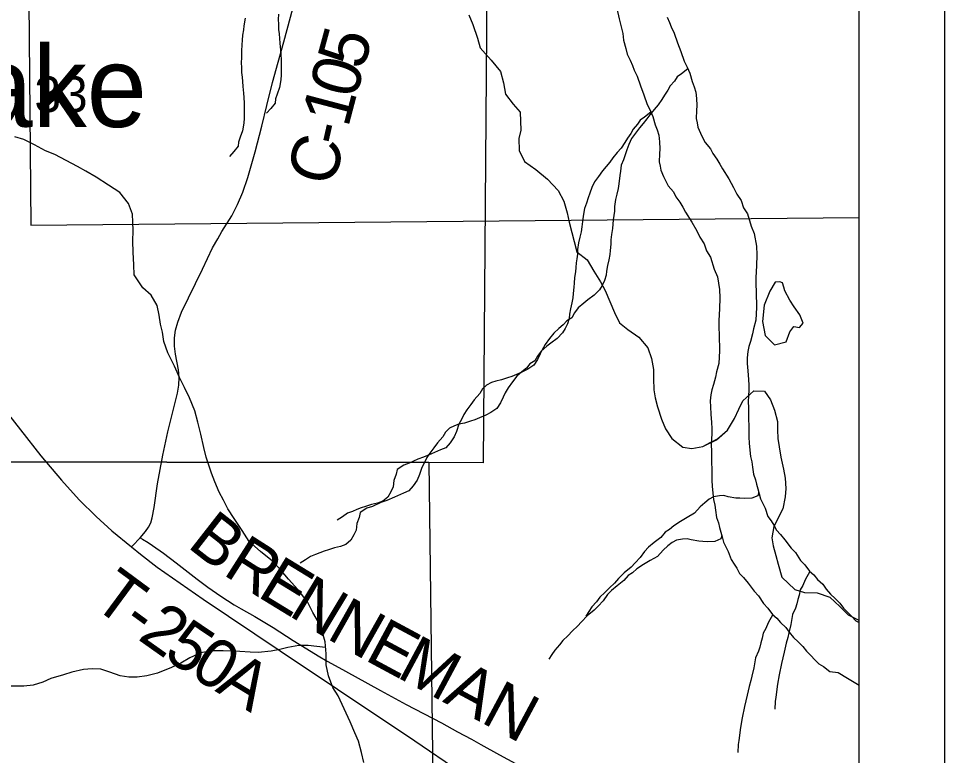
# Model space of a CAD drawing. Extents: x -21.1 to 50.3, y -4.9 to 22.1.
# Drawn here: x 7.916 to 9, y 16.789 to 17.651 of the extents above; entities that cross this region are included whole.
import ezdxf

# ---------------------------------------------------------------- set-up
doc = ezdxf.new("R2010")
doc.units = 0
for name, color, linetype in [('GM_X_Corporation', 7, 'Continuous'), ('GM_X_County', 7, 'Continuous'), ('GM_X_County_Road', 7, 'Continuous'), ('GM_X_County_Road_Text', 7, 'Continuous'), ('GM_X_Major_Lake', 7, 'Continuous'), ('GM_X_Major_Lake_Text', 7, 'Continuous'), ('GM_X_Minor_River', 7, 'Continuous'), ('GM_X_Rail_Line_Text', 7, 'Continuous'), ('GM_X_Section', 7, 'Continuous'), ('GM_X_Section_Text', 7, 'Continuous'), ('GM_X_Township_Road', 7, 'Continuous'), ('GM_X_Township_Road_Text', 7, 'Continuous'), ('GM_X_US_Route', 7, 'Continuous'), ('SH_Cut_Line', 7, 'Continuous'), ('SH_Data', 7, 'Continuous')]:
    doc.layers.add(name, color=color, linetype=linetype)

msp = doc.modelspace()

# ---------------------------------------------------------------- linework, layer by layer
at = {"layer": 'GM_X_Corporation'}
msp.add_lwpolyline([(8.9, 17.418), (8.9, 18.4235), (7.9213, 18.4125), (7.9303, 17.4089)], close=True, dxfattribs=at)
at = {"layer": 'GM_X_County'}
msp.add_lwpolyline([(8.9, 14.7464), (8.9, 20.9), (2.1, 20.9), (2.1, 14.1), (8.8932, 14.1)], dxfattribs=at)
at = {"layer": 'GM_X_County_Road'}
for points in [[(8.0586, 17.0433), (8.0647, 17.0505), (8.0681, 17.0555), (8.0708, 17.0609), (8.0726, 17.0667), (8.0748, 17.0788), (8.0788, 17.1064), (8.0851, 17.14), (8.0908, 17.1673), (8.102, 17.2126), (8.1036, 17.2217), (8.1041, 17.2308), (8.1032, 17.2399), (8.0997, 17.2582), (8.0986, 17.2676), (8.0986, 17.277), (8.0998, 17.2863), (8.1024, 17.2954), (8.107, 17.307), (8.1313, 17.3573), (8.1432, 17.3824), (8.1492, 17.3931), (8.1542, 17.4014), (8.1656, 17.4197), (8.1725, 17.4333), (8.1785, 17.4474), (8.1846, 17.4649), (8.1932, 17.4946), (8.201, 17.5247), (8.2067, 17.5488), (8.2134, 17.5758), (8.2266, 17.6235), (8.2411, 17.6773)], [(8.0482, 17.0326), (8.0493, 17.0337), (8.0586, 17.0433)]]:
    msp.add_lwpolyline(points, dxfattribs=at)
at = {"layer": 'GM_X_Major_Lake'}
for points in [[(8.4431, 17.6549), (8.4477, 17.6439), (8.4534, 17.6279), (8.4564, 17.6166), (8.4693, 17.6018), (8.4802, 17.5889), (8.4836, 17.5756), (8.4863, 17.5623), (8.495, 17.5506), (8.5033, 17.5411), (8.5039, 17.5201)], [(8.5039, 17.5201), (8.5016, 17.5103), (8.5023, 17.4962), (8.5082, 17.4833), (8.5215, 17.4741), (8.5354, 17.4626), (8.5479, 17.4496), (8.5542, 17.4371), (8.5583, 17.4234), (8.5605, 17.4124), (8.5698, 17.3776)], [(8.5698, 17.3776), (8.5819, 17.3683), (8.5894, 17.3553), (8.5973, 17.3427), (8.6029, 17.3325), (8.6081, 17.3195), (8.6137, 17.3066), (8.6197, 17.2948), (8.6295, 17.2868), (8.642, 17.278), (8.6529, 17.2654), (8.657, 17.2529), (8.6592, 17.24), (8.6595, 17.2297), (8.6598, 17.2164), (8.6613, 17.2069), (8.6639, 17.1963), (8.6687, 17.1819), (8.6736, 17.1708), (8.6807, 17.1594), (8.6936, 17.1491), (8.7042, 17.1475), (8.7171, 17.1501), (8.7332, 17.1579)], [(8.5698, 17.3776), (8.5819, 17.3683), (8.5894, 17.3553), (8.5973, 17.3427), (8.6029, 17.3325), (8.6081, 17.3195), (8.6137, 17.3066), (8.6197, 17.2948), (8.6295, 17.2868), (8.642, 17.278), (8.6529, 17.2654), (8.657, 17.2529), (8.6592, 17.24), (8.6595, 17.2297), (8.6598, 17.2164), (8.6613, 17.2069), (8.6639, 17.1963), (8.6687, 17.1819), (8.6736, 17.1708), (8.6807, 17.1594), (8.6936, 17.1491), (8.7042, 17.1475), (8.7171, 17.1501), (8.7266, 17.155)], [(8.5698, 17.3776), (8.5819, 17.3683), (8.5894, 17.3553), (8.5973, 17.3427), (8.6029, 17.3325), (8.6081, 17.3195), (8.6137, 17.3066), (8.6197, 17.2948), (8.6295, 17.2868), (8.642, 17.278), (8.6529, 17.2654), (8.657, 17.2529), (8.6592, 17.24), (8.6595, 17.2297), (8.6598, 17.2164), (8.6613, 17.2069), (8.6639, 17.1963), (8.6687, 17.1819), (8.6736, 17.1708), (8.6807, 17.1594), (8.6936, 17.1491), (8.7042, 17.1475), (8.7171, 17.1501), (8.7343, 17.1589)], [(8.8018, 17.3421), (8.7957, 17.3318), (8.7888, 17.3155), (8.7869, 17.2961), (8.7899, 17.2798), (8.8009, 17.2688), (8.8146, 17.2726), (8.8188, 17.2843), (8.8237, 17.2904), (8.8302, 17.2893), (8.8347, 17.2942), (8.8306, 17.3041), (8.8241, 17.3136), (8.8188, 17.3212)], [(8.8188, 17.3212), (8.8132, 17.3322), (8.8121, 17.3366), (8.8102, 17.3414), (8.8073, 17.3428), (8.8018, 17.3421)], [(8.7332, 17.1579), (8.7458, 17.1693), (8.7541, 17.1826), (8.7591, 17.1936), (8.764, 17.2035), (8.7769, 17.2152), (8.7895, 17.2148), (8.7963, 17.2046), (8.8012, 17.1924), (8.8046, 17.1791), (8.8046, 17.1696), (8.805, 17.1594), (8.8065, 17.1495), (8.8084, 17.1377), (8.8114, 17.1237), (8.8136, 17.1131), (8.8144, 17.1009), (8.8136, 17.091), (8.8106, 17.077), (8.8003, 17.0565), (8.798, 17.0432), (8.7995, 17.0337), (8.8025, 17.0227), (8.8052, 17.0124), (8.8097, 16.9972), (8.8249, 16.9828), (8.8363, 16.9794), (8.8511, 16.979), (8.8659, 16.9737), (8.8776, 16.963), (8.8871, 16.9531), (8.8974, 16.9482), (8.9, 16.9464)], [(8.7343, 17.1589), (8.7458, 17.1693), (8.7541, 17.1826), (8.7591, 17.1936), (8.764, 17.2035), (8.7769, 17.2152), (8.7895, 17.2148), (8.7963, 17.2046), (8.8012, 17.1924), (8.8046, 17.1791), (8.8046, 17.1696), (8.805, 17.1594), (8.8065, 17.1495), (8.8084, 17.1377), (8.8114, 17.1237), (8.8136, 17.1131), (8.8144, 17.1009), (8.8136, 17.091), (8.8106, 17.077), (8.8003, 17.0565), (8.798, 17.0432), (8.7995, 17.0337), (8.8025, 17.0227), (8.8052, 17.0124), (8.8097, 16.9972), (8.8249, 16.9828), (8.8363, 16.9794), (8.8511, 16.979), (8.8659, 16.9737), (8.8776, 16.963), (8.8871, 16.9531), (8.8974, 16.9482), (8.9, 16.9464)]]:
    msp.add_lwpolyline(points, dxfattribs=at)
at = {"layer": 'GM_X_Minor_River'}
for points in [[(8.6163, 17.6625), (8.619, 17.6503), (8.6218, 17.6393), (8.6233, 17.6333), (8.6241, 17.6253), (8.6268, 17.6158), (8.6284, 17.609), (8.6319, 17.6018), (8.6346, 17.5957), (8.6369, 17.5904), (8.6403, 17.5832), (8.6442, 17.5718), (8.6481, 17.5616), (8.6519, 17.5502), (8.6554, 17.5434), (8.6585, 17.5362), (8.6612, 17.5263), (8.6635, 17.5203), (8.6655, 17.5142), (8.6663, 17.5066), (8.6667, 17.4983), (8.6664, 17.4926), (8.666, 17.4831), (8.6672, 17.4781), (8.668, 17.4732), (8.6711, 17.466), (8.6738, 17.4603), (8.6765, 17.455), (8.6826, 17.4478), (8.6857, 17.4421), (8.6903, 17.4357), (8.6937, 17.43), (8.6968, 17.4243), (8.7041, 17.4126), (8.7099, 17.4024), (8.7137, 17.3948), (8.7187, 17.3872), (8.7214, 17.3789), (8.726, 17.3717), (8.7303, 17.3573), (8.7341, 17.3486), (8.7365, 17.3338), (8.7369, 17.3239), (8.7366, 17.311), (8.736, 17.2973), (8.736, 17.2893), (8.7364, 17.2806), (8.7365, 17.262), (8.7359, 17.2472), (8.7332, 17.2373), (8.7321, 17.2312), (8.7295, 17.2224), (8.7276, 17.2163), (8.7265, 17.2106), (8.7258, 17.2034), (8.7259, 17.1966), (8.7263, 17.1878), (8.7271, 17.178), (8.7275, 17.1711), (8.7276, 17.1662), (8.7272, 17.1578), (8.7269, 17.1525), (8.7273, 17.1442), (8.7275, 17.1107), (8.7279, 17.1031), (8.7295, 17.0879), (8.7311, 17.0815), (8.7319, 17.0754), (8.7331, 17.0671), (8.7354, 17.0606), (8.7365, 17.0553), (8.7381, 17.05), (8.7396, 17.0443), (8.7412, 17.0382), (8.7466, 17.0273), (8.7501, 17.0178), (8.7539, 17.0125), (8.757, 17.0076), (8.7601, 17.0015), (8.7647, 16.9966), (8.77, 16.9902), (8.7773, 16.9807), (8.7823, 16.9754), (8.788, 16.9663), (8.7934, 16.961), (8.7988, 16.9535), (8.8037, 16.9493), (8.808, 16.944), (8.8141, 16.9384), (8.8183, 16.9327), (8.8233, 16.9266), (8.8286, 16.9217), (8.834, 16.9161), (8.8386, 16.9104), (8.8436, 16.9055)], [(8.1813, 17.6513), (8.1798, 17.6422), (8.1795, 17.6373), (8.1784, 17.6312), (8.178, 17.6255), (8.1773, 17.6198), (8.1769, 17.6129), (8.177, 17.6053), (8.1766, 17.5989), (8.177, 17.5936), (8.1771, 17.5875), (8.1779, 17.5822), (8.1783, 17.5769), (8.1787, 17.5712), (8.1795, 17.5632), (8.1799, 17.5583), (8.1803, 17.5518), (8.18, 17.5457), (8.18, 17.5343), (8.1797, 17.5282), (8.1782, 17.5195), (8.1756, 17.5119), (8.1737, 17.5062), (8.173, 17.5012), (8.1681, 17.4951), (8.1632, 17.4894)], [(8.2203, 17.6559), (8.2199, 17.6494), (8.2203, 17.6441), (8.2204, 17.638), (8.2212, 17.6327), (8.2216, 17.6274), (8.222, 17.6217), (8.2228, 17.6137), (8.2232, 17.6088), (8.2236, 17.6023), (8.2233, 17.5962), (8.2233, 17.5848), (8.223, 17.5788), (8.2215, 17.57), (8.2189, 17.5624), (8.217, 17.5567), (8.2163, 17.5518), (8.2114, 17.5456), (8.2064, 17.5399)], [(8.6752, 17.6523), (8.6779, 17.6462), (8.6802, 17.6409), (8.6836, 17.6337), (8.6875, 17.6224), (8.6914, 17.6121), (8.6952, 17.6007), (8.6987, 17.5939), (8.7018, 17.5867), (8.7045, 17.5769), (8.7068, 17.5708), (8.7088, 17.5647), (8.7096, 17.5571), (8.71, 17.5488), (8.7096, 17.5431), (8.7093, 17.5336), (8.7105, 17.5286), (8.7113, 17.5237), (8.7144, 17.5165), (8.7171, 17.5108), (8.7197, 17.5055), (8.7259, 17.4983), (8.729, 17.4927), (8.7336, 17.4862), (8.737, 17.4805), (8.7401, 17.4749), (8.7474, 17.4631), (8.7532, 17.4529), (8.757, 17.4453), (8.762, 17.4378), (8.7647, 17.4294), (8.7693, 17.4222), (8.7736, 17.4078), (8.7774, 17.3991), (8.7798, 17.3843), (8.7802, 17.3744), (8.7799, 17.3615), (8.7792, 17.3478), (8.7793, 17.3398), (8.7797, 17.3311), (8.7798, 17.3125), (8.7791, 17.2977), (8.7765, 17.2878), (8.7754, 17.2817), (8.7728, 17.2729), (8.7709, 17.2669), (8.7698, 17.2612), (8.7691, 17.2539), (8.7691, 17.2471), (8.7696, 17.2384), (8.7704, 17.2285), (8.7708, 17.2216), (8.7708, 17.2167), (8.7705, 17.2084), (8.7702, 17.203), (8.7706, 17.1947), (8.7708, 17.1612), (8.7712, 17.1537), (8.7728, 17.1385), (8.7744, 17.132), (8.7752, 17.1259), (8.7763, 17.1176), (8.7787, 17.1111), (8.7798, 17.1058), (8.7814, 17.1005), (8.7829, 17.0948), (8.7845, 17.0888), (8.7899, 17.0778), (8.7934, 17.0683), (8.7972, 17.063), (8.8003, 17.0581), (8.8034, 17.052), (8.8079, 17.0471), (8.8133, 17.0407), (8.8206, 17.0312), (8.8256, 17.0259), (8.8313, 17.0168), (8.8367, 17.0116), (8.8421, 17.004), (8.847, 16.9998), (8.8513, 16.9945), (8.8574, 16.9889), (8.8616, 16.9832), (8.8666, 16.9772), (8.8719, 16.9722), (8.8773, 16.9666), (8.8819, 16.9609), (8.8869, 16.956)], [(8.6996, 17.5917), (8.6923, 17.5859), (8.687, 17.5825), (8.6839, 17.5775), (8.679, 17.5718), (8.676, 17.5668), (8.6722, 17.5611), (8.6692, 17.5561), (8.6647, 17.5497), (8.6601, 17.5443), (8.6552, 17.5382), (8.6515, 17.5333), (8.6473, 17.5279), (8.6431, 17.523), (8.6382, 17.5165), (8.6337, 17.5104), (8.6303, 17.5035), (8.6281, 17.497), (8.6262, 17.4913), (8.6243, 17.4852), (8.6217, 17.4791), (8.6206, 17.4723), (8.6199, 17.467), (8.6188, 17.4575), (8.618, 17.4518), (8.6165, 17.4453), (8.6147, 17.4388), (8.6136, 17.4309), (8.6136, 17.4255), (8.6129, 17.4202), (8.6121, 17.4153), (8.6118, 17.41), (8.6114, 17.405), (8.6103, 17.3982), (8.6096, 17.3917), (8.6093, 17.3868), (8.6085, 17.3795), (8.6082, 17.3746), (8.6071, 17.3685), (8.6056, 17.3617), (8.6045, 17.3552), (8.6038, 17.3503), (8.6019, 17.3442), (8.5993, 17.3385), (8.5962, 17.3335), (8.5898, 17.327), (8.5826, 17.3217), (8.5777, 17.3178), (8.5712, 17.3121), (8.5667, 17.3064), (8.5637, 17.3007), (8.558, 17.2972), (8.5538, 17.2922), (8.5485, 17.288), (8.5425, 17.2827), (8.5376, 17.2762), (8.5326, 17.2693), (8.5289, 17.2632), (8.5266, 17.2583), (8.5236, 17.2518), (8.5191, 17.245), (8.5123, 17.2404), (8.5062, 17.2373), (8.499, 17.2342), (8.4936, 17.2319), (8.4883, 17.2303), (8.4815, 17.228), (8.4746, 17.2265), (8.4697, 17.2249), (8.464, 17.2219), (8.4591, 17.2173), (8.4561, 17.2119), (8.4496, 17.2047), (8.4455, 17.199), (8.441, 17.1929), (8.4372, 17.1875), (8.4345, 17.1818), (8.4315, 17.1761), (8.4289, 17.1677), (8.4259, 17.1612), (8.4214, 17.1544), (8.4161, 17.1486), (8.41, 17.146), (8.3994, 17.1413), (8.3903, 17.1375), (8.3834, 17.1352), (8.3735, 17.1306), (8.3671, 17.1282), (8.3591, 17.1233), (8.358, 17.1176), (8.3554, 17.1103), (8.3547, 17.1027), (8.3517, 17.097), (8.3483, 17.0909), (8.3426, 17.0859), (8.3361, 17.0836), (8.3293, 17.0821), (8.3221, 17.0798), (8.3171, 17.0782), (8.3122, 17.0763), (8.3069, 17.074)], [(8.6564, 17.5412), (8.649, 17.5354), (8.6437, 17.5319), (8.6407, 17.527), (8.6357, 17.5213), (8.6327, 17.5163), (8.6289, 17.5106), (8.6259, 17.5056), (8.6214, 17.4992), (8.6169, 17.4938), (8.6119, 17.4877), (8.6082, 17.4827), (8.604, 17.4774), (8.5998, 17.4724), (8.5949, 17.466), (8.5904, 17.4598), (8.587, 17.453), (8.5848, 17.4465), (8.5829, 17.4408), (8.581, 17.4347), (8.5784, 17.4286), (8.5773, 17.4218), (8.5766, 17.4165), (8.5755, 17.407), (8.5747, 17.4013), (8.5733, 17.3948), (8.5714, 17.3883), (8.5703, 17.3803), (8.5703, 17.375), (8.5696, 17.3697), (8.5689, 17.3648), (8.5685, 17.3594), (8.5682, 17.3545), (8.567, 17.3477), (8.5663, 17.3412), (8.566, 17.3363), (8.5652, 17.329), (8.5649, 17.3241), (8.5638, 17.318), (8.5623, 17.3112), (8.5612, 17.3047), (8.5605, 17.2998), (8.5586, 17.2937), (8.556, 17.288), (8.5529, 17.283), (8.5465, 17.2765), (8.5393, 17.2711), (8.5344, 17.2673), (8.5279, 17.2616), (8.5234, 17.2559), (8.5204, 17.2501), (8.5147, 17.2467), (8.5105, 17.2417), (8.5052, 17.2375), (8.4992, 17.2322), (8.4943, 17.2257), (8.4894, 17.2188), (8.4856, 17.2127), (8.4833, 17.2078), (8.4803, 17.2013), (8.4758, 17.1944), (8.469, 17.1898), (8.4629, 17.1868), (8.4557, 17.1837), (8.4504, 17.1814), (8.445, 17.1798), (8.4382, 17.1775), (8.4314, 17.176), (8.4264, 17.1744), (8.4207, 17.1713), (8.4158, 17.1668), (8.4128, 17.1614), (8.4064, 17.1542), (8.4022, 17.1484), (8.3977, 17.1423), (8.3939, 17.137), (8.3913, 17.1313), (8.3882, 17.1256), (8.3856, 17.1172), (8.3826, 17.1107), (8.3781, 17.1039), (8.3728, 17.0981), (8.3667, 17.0954), (8.3561, 17.0908), (8.347, 17.087), (8.3401, 17.0847), (8.3303, 17.08), (8.3238, 17.0777), (8.3158, 17.0727), (8.3147, 17.067), (8.3121, 17.0598), (8.3114, 17.0522), (8.3084, 17.0465), (8.305, 17.0404), (8.2993, 17.0354), (8.2928, 17.0331), (8.286, 17.0316), (8.2788, 17.0292), (8.2738, 17.0277), (8.2689, 17.0258), (8.2636, 17.0235)], [(8.3203, 16.7803), (8.3177, 16.792), (8.314, 16.8053), (8.3099, 16.8152), (8.3043, 16.8278), (8.2994, 16.8381), (8.295, 16.8483), (8.2901, 16.8582), (8.2841, 16.8681), (8.2789, 16.8818), (8.2763, 16.8947), (8.276, 16.9076), (8.275, 16.9217), (8.2712, 16.935), (8.2671, 16.9445), (8.2604, 16.9559), (8.2544, 16.9685), (8.2431, 16.9826), (8.2322, 16.9948), (8.2235, 17.0051), (8.2133, 17.0158), (8.1994, 17.0272), (8.1862, 17.0387), (8.1779, 17.0517), (8.1685, 17.0658), (8.161, 17.0772), (8.1558, 17.0871), (8.1509, 17.0966), (8.1457, 17.1088), (8.1419, 17.1187), (8.1389, 17.1282), (8.1356, 17.1377), (8.133, 17.1487), (8.1293, 17.1646), (8.126, 17.1783), (8.1223, 17.1916), (8.1163, 17.2068), (8.1103, 17.219), (8.1043, 17.2308), (8.0987, 17.2441), (8.0909, 17.2597), (8.086, 17.273), (8.0846, 17.2837), (8.0824, 17.2932), (8.0805, 17.3038), (8.0783, 17.3148), (8.0712, 17.327), (8.0614, 17.3358), (8.0516, 17.351), (8.0509, 17.3624), (8.0503, 17.3772), (8.05, 17.3901), (8.0501, 17.4026), (8.0498, 17.4125), (8.0494, 17.422), (8.0446, 17.4342), (8.0348, 17.4471), (8.0212, 17.4559), (8.0068, 17.4651), (7.9947, 17.472), (7.9849, 17.4774), (7.9717, 17.4847), (7.9584, 17.4916), (7.9475, 17.4958), (7.9346, 17.5028), (7.9221, 17.5093), (7.9119, 17.5124)], [(8.7825, 17.0965), (8.7814, 17.0925), (8.7746, 17.0895), (8.7658, 17.089), (8.7605, 17.0894), (8.7556, 17.0897), (8.7468, 17.0912), (8.7418, 17.0927), (8.7365, 17.0923), (8.7297, 17.0911), (8.7244, 17.0884), (8.7194, 17.0842), (8.7141, 17.0793), (8.7073, 17.072), (8.6986, 17.067), (8.691, 17.0624), (8.683, 17.0574), (8.6781, 17.0528), (8.6732, 17.0498), (8.6679, 17.0437), (8.6603, 17.0376), (8.6535, 17.0322), (8.6489, 17.0272), (8.6437, 17.02), (8.638, 17.0139), (8.6331, 17.0089), (8.6251, 17.0024), (8.6183, 16.9955), (8.6138, 16.9902), (8.6077, 16.9848), (8.6024, 16.9791), (8.5967, 16.9738), (8.5926, 16.9684), (8.5873, 16.9623), (8.5835, 16.957), (8.5801, 16.9516)], [(8.3069, 17.074), (8.3012, 17.072), (8.2951, 17.0678), (8.289, 17.064)], [(8.7392, 17.046), (8.7381, 17.042), (8.7313, 17.039), (8.7226, 17.0385), (8.7172, 17.0389), (8.7123, 17.0392), (8.7035, 17.0407), (8.6986, 17.0422), (8.6932, 17.0418), (8.6864, 17.0406), (8.6811, 17.0379), (8.6761, 17.0337), (8.6708, 17.0287), (8.664, 17.0215), (8.6553, 17.0165), (8.6477, 17.0119), (8.6398, 17.0069), (8.6348, 17.0023), (8.6299, 16.9993), (8.6246, 16.9932), (8.617, 16.987), (8.6102, 16.9817), (8.6057, 16.9767), (8.6004, 16.9695), (8.5947, 16.9634), (8.5898, 16.9584), (8.5818, 16.9519), (8.575, 16.945), (8.5705, 16.9397), (8.5644, 16.9343), (8.5591, 16.9286), (8.5534, 16.9232), (8.5493, 16.9179), (8.544, 16.9118), (8.5402, 16.9065), (8.5368, 16.9011)], [(8.2636, 17.0235), (8.2579, 17.0215), (8.2518, 17.0173), (8.2457, 17.0135)], [(8.8423, 17.0038), (8.8368, 16.9941), (8.8342, 16.9876), (8.8311, 16.9823), (8.8297, 16.9762), (8.8282, 16.9709), (8.8271, 16.9659), (8.8256, 16.961), (8.8222, 16.9534), (8.82, 16.9416), (8.8177, 16.9321), (8.8166, 16.9267), (8.8147, 16.9199), (8.8125, 16.9096), (8.8107, 16.9028), (8.8092, 16.8963), (8.8066, 16.883), (8.8047, 16.872), (8.8025, 16.8568), (8.8018, 16.8518), (8.8015, 16.8427)], [(8.8869, 16.956), (8.8915, 16.9511), (8.8961, 16.9462), (8.9, 16.9441)], [(8.799, 16.9533), (8.7935, 16.9436), (8.7909, 16.9371), (8.7879, 16.9318), (8.7864, 16.9257), (8.7849, 16.9203), (8.7838, 16.9154), (8.7823, 16.9105), (8.7789, 16.9028), (8.7767, 16.8911), (8.7744, 16.8815), (8.7733, 16.8762), (8.7715, 16.8694), (8.7692, 16.8591), (8.7674, 16.8523), (8.7659, 16.8458), (8.7633, 16.8325), (8.7614, 16.8214), (8.7593, 16.8062), (8.7585, 16.8013), (8.7582, 16.7922)], [(8.2755, 16.9148), (8.2651, 16.916), (8.2552, 16.9172), (8.2442, 16.9173), (8.2313, 16.9147), (8.2218, 16.9125), (8.2119, 16.9107), (8.1967, 16.9089), (8.1872, 16.9093), (8.1751, 16.9102), (8.1656, 16.9106), (8.1554, 16.911), (8.1421, 16.9111), (8.1295, 16.9085), (8.1166, 16.9029), (8.1059, 16.8965), (8.0953, 16.8913), (8.0789, 16.8849), (8.0664, 16.8816), (8.055, 16.8802), (8.0451, 16.8802), (8.0352, 16.8818), (8.0231, 16.886), (8.0125, 16.8895), (8.0023, 16.89), (7.992, 16.8893), (7.9784, 16.8859), (7.9685, 16.883), (7.954, 16.8785), (7.9445, 16.8744), (7.9331, 16.8707), (7.9221, 16.8696), (7.9073, 16.8697)], [(8.8436, 16.9055), (8.8482, 16.9006), (8.8528, 16.8957), (8.8585, 16.8926), (8.8657, 16.8869)], [(8.8657, 16.8869), (8.8757, 16.8856), (8.8864, 16.8792), (8.8963, 16.8732), (8.9, 16.8708)]]:
    msp.add_lwpolyline(points, dxfattribs=at)
at = {"layer": 'GM_X_Rail_Line_Text'}
msp.add_lwpolyline([(8.9, 16.4052), (8.9, 20.435)], dxfattribs=at)
at = {"layer": 'GM_X_Section'}
for points in [[(7.4621, 18.1346), (8.4678, 18.1394), (8.46, 17.1311), (8.3964, 17.1315), (7.4753, 17.1323)], [(7.4071, 17.132), (7.4753, 17.1323), (8.3964, 17.1315), (8.4094, 16.1114), (7.4213, 16.1221)]]:
    msp.add_lwpolyline(points, close=True, dxfattribs=at)
at = {"layer": 'GM_X_Township_Road'}
msp.add_lwpolyline([(8.0586, 17.0433), (8.0611, 17.0418), (8.0679, 17.0378), (8.073, 17.0342), (8.0856, 17.0251), (8.1005, 17.0139), (8.125, 16.9948), (8.1375, 16.9855), (8.1528, 16.9749), (8.1685, 16.9648), (8.1765, 16.9601), (8.1928, 16.9511), (8.2141, 16.9381), (8.2377, 16.9232), (8.2535, 16.9133), (8.2667, 16.9053), (8.2775, 16.899), (8.291, 16.8914), (8.31, 16.8809), (8.3399, 16.8645), (8.3699, 16.8483), (8.411, 16.8267), (8.43, 16.8164), (8.4463, 16.8075), (8.4571, 16.8014), (8.4789, 16.7895), (8.5116, 16.7716)], dxfattribs=at)
at = {"layer": 'GM_X_US_Route'}
msp.add_lwpolyline([(7.8941, 17.2001), (7.942, 17.1391), (7.9662, 17.1105), (7.9871, 17.0878), (8.007, 17.0683), (8.0254, 17.0515), (8.0482, 17.0326), (8.0587, 17.0239), (8.0785, 17.0088), (8.1322, 16.9713), (8.2225, 16.9111), (8.2893, 16.8661), (8.3798, 16.8057), (8.4854, 16.734)], dxfattribs=at)
at = {"layer": 'SH_Cut_Line'}
msp.add_lwpolyline([(8.9, 16.4052), (8.9, 20.9), (2.1, 20.9)], dxfattribs=at)
at = {"layer": 'SH_Data'}
msp.add_line((9, 21), (9, 14), dxfattribs=at)

# ---------------------------------------------------------------- texts
at = {"layer": 'GM_X_County_Road_Text'}
for s, rotation, p in [('5', 74.7065, (8.3198, 17.5894)), ('0', 74.7766, (8.3106, 17.5556)), ('1', 75.2291, (8.3017, 17.5219)), ('-', 77.1954, (8.2966, 17.4997)), ('C', 75.188, (8.2842, 17.4524))]:
    msp.add_text(s, height=0.0568, rotation=rotation, dxfattribs=at).set_placement(p)
at = {"layer": 'GM_X_Major_Lake_Text'}
msp.add_text('Lake', height=0.09472, rotation=359.9981, dxfattribs=at).set_placement((7.7917, 17.5238))
at = {"layer": 'GM_X_Section_Text'}
msp.add_text('33', height=0.04186, rotation=0, dxfattribs=at).set_placement((7.9346, 17.5412))
at = {"layer": 'GM_X_Township_Road_Text'}
for s, rotation, p in [('B', 322.0138, (8.1122, 17.0333)), ('R', 327.4694, (8.1538, 17.0011)), ('E', 328.573, (8.1941, 16.9754)), ('T', 323.5501, (8.0002, 16.9649)), ('N', 328.8778, (8.2307, 16.9531)), ('N', 330.541, (8.2751, 16.9263)), ('-', 323.8729, (8.0347, 16.9395)), ('2', 324.7667, (8.0543, 16.9252)), ('5', 326.0974, (8.0841, 16.9041)), ('E', 331.7106, (8.3197, 16.9011)), ('0', 327.5697, (8.1145, 16.8837)), ('M', 331.7875, (8.3572, 16.881)), ('A', 328.7731, (8.1451, 16.8643)), ('A', 331.79, (8.4115, 16.8518)), ('N', 331.79, (8.4556, 16.8282))]:
    msp.add_text(s, height=0.0568, rotation=rotation, dxfattribs=at).set_placement(p)

doc.saveas('drawing.dxf')
